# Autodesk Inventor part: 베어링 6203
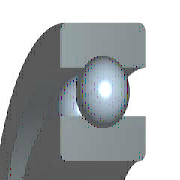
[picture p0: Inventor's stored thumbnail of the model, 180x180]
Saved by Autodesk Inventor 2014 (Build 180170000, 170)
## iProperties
IsCustomPart: 0
Created: 2016-05
Part Number: 베어링 6203
Material: 강철, 연강
Description: 깊은 그루브 볼 베어링
Document SubType Name: Modeling
Standard: KS B 2023
Designer: mduedu
Standards Organization: KS
Language: ko-KR
Size Designation: 6203 - 17 x 40 x 12
Categories: <MemberInstance><Categories><Category DisplayName="샤프트 부품" InternalName="7f7aeb1f-a693-4053-b835-cee3144e0d98" Mnemonic="SHFT"><Category DisplayName="베어링" Inter
Density: 1 g/cm^3
Appearance: Yellow
Author: mduedu
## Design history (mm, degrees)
sketch "스케치" dims "d0" = 5.98 (= -0.26 x WD + 0.26 x BD)
  geometry: L1 (3.01, 14.25)-(8.99, 14.25); L2 (6, 14.25)-(6, 11.26); L3 (6, 14.25)-(6, 17.24); L4 (3.778, 12.249)-(0, 12.249); L5 (0, 8.5)-(12, 8.5); L6 (3.778, 16.251)-(0, 16.251); L7 (0, 20)-(12, 20); L8 (12, 8.5)-(12, 12.249); L9 (8.222, 12.249)-(12, 12.249); L10 (8.222, 16.251)-(12, 16.251); L11 (12, 20)-(12, 16.251); L12 (-1.4, 0)-(8.4, 0) reference; L13 (0, -0.3)-(0, 5.3) reference
  constraints: 22 end point, 4 point on line, 2 collinear, 2 perpendicular, 2 symmetric about line, 1 midpoint, 1 parallel, 14 other
  dimensions: "d9" = 17 diameter of L5 L12 (= WD); "d11" = 40 diameter of L7 L12 (= BD); "d12" = 12 distance between parallel lines of L8 L13 (= KB); "d13" = 24.498 diameter of L9 L12 (= 0.326 x BD + 0.674 x WD)
revolve "본체" stored, may be unused: angle "d6" = 90 deg
revolve "볼" stored, may be unused: angle "d7" = 90 deg
pattern_circular "IDS_ARRAYBALL[SIMPL:T]" dims angle "d3" = 360 deg
body "Solid1"
fillet "모깎기1" dims "d1" = 0.6 (= KRS)
other parameters: "WD" = 17 [user parameter; used in 5 equation terms], "BD" = 40 [user parameter; used in 5 equation terms], "KB" = 12 [user parameter; used in 1 equation term], "KRS" = 0.6 [user parameter; used in 1 equation term], "d4" = 0, "d5" = 0, "d8" = 0, "d14" = 0, "d15" = 0, "BBA" = 0 [user parameter], "BC0" = 4750000 [user parameter], "BC" = 9560000 [user parameter], "WR" = 8.5 (= 0.5 x WD) [user parameter]
